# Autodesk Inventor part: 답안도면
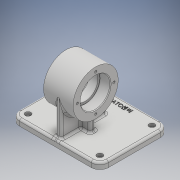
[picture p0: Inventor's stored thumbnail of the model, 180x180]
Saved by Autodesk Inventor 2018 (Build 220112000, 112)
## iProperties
Created: 2019-09
Part Number: 답안도면
Material: 일반
Document SubType Name: Modeling
Designer: USER
Density: 1 g/cm^3
Appearance: 기본값
Mass: 205.424 g
Surface Area: 495.891 cm^2
Volume: 205.424 cm^3
Author: USER
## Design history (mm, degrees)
sketch "스케치1"
  geometry: L1 (0, 0)-(42, 0); L2 (0, 0)-(0, 32); L3 (0, 32)-(42, 32); L4 (42, 32)-(42, 0); L5 (0, 21)-(15, 21); L6 (15, 21)-(15, 18); L7 (15, 18)-(27, 18); L8 (27, 18)-(27, 21); L9 (27, 21)-(42, 21)
  constraints: 18 end point, 4 perpendicular, 4 point on line, 3 horizontal, 1 vertical
  dimensions: "d0" = 42 distance of L1.start L1.end; "d1" = 42 diameter of L5 L1; "d2" = 64 diameter of L3 L1; "d3" = 36 diameter of L7 L1; "d4" = 15 distance between parallel lines of L2 L6; "d5" = 15 distance between parallel lines of L4 L8
revolve "회전1" sketch "스케치1" stored, may be unused: angle "d6" = 90 deg
node "작업 평면1"
sketch "스케치2"
  geometry: L1 (0, 32)-(42, 32) reference; L2 (21, 32)-(21, -32); L3 (0, -32)-(42, -32) reference; L4 (42, -21)-(42, 21) reference; L5 (0, -21)-(0, 21) reference; L6 (0, 0)-(42, 0); L7 (21, 0)-(84, 0); L8 (84, 0)-(84, 62); L9 (84, 62)-(-42, 62); L10 (-42, 62)-(-42, -36); L11 (-42, -36)-(84, -36); L12 (84, -36)-(84, 0); 2 further points
  constraints: 16 end point, 5 midpoint, 3 perpendicular, 1 point on line, 1 vertical
  dimensions: "d8" = 63 distance of L7.start L7.end; "d9" = 62 distance of L7.end L8.end; "d10" = 126 distance of L8.end L9.end; "d11" = 98 distance of L9.end L10.end; "d12" = 126 distance of L10.end L11.end
extrude "돌출1" join sketch "스케치2" distance "d13" = 9; taper "d14" = 0 deg
sketch "스케치3"
  geometry: L1 (0, -32)-(-42, -32) reference; L2 (-21, -32)-(-21, -50); L3 (-21, -50)-(-4, -50); L4 (-4, -50)-(-4, -32); L5 (-21, -50)-(-38, -50); L6 (-38, -50)-(-38, -32); L7 (-4, -32)-(-38, -32); L8 (-4, -32)-(-4, -28.095); L9 (-4, -28.095)-(-38, -28.095); L10 (-38, -28.095)-(-38, -32); 1 further point
  constraints: 18 end point, 4 perpendicular, 2 point on line, 1 collinear, 1 midpoint, 1 vertical
  dimensions: "d15" = 17 distance of L2.end L3.end; "d16" = 17 distance of L2.end L5.end
extrude "돌출2" join sketch "스케치3" stored distance "d17" = 8; taper "d18" = 0 deg
node "작업 평면2"
sketch "스케치4"
  geometry: L1 (62, -50)-(-36, -50) reference; L2 (62, -59)-(-36, -59) reference; L3 (-36, -59)-(-36, -50) reference; L4 (62, -50)-(-36, -50) reference; L5 (62, -59)-(62, -50) reference; L6 (32, 0)-(32, -50); L7 (-32, 0)-(-32, -50); L8 (32, -50)-(-32, -50); C1 r 32 at (0, 0) reference; A1 r 32 centre (0, 0) between (32, 0) and (-32, 0) reference; 1 further point
  constraints: 6 end point, 4 tangent, 2 perpendicular, 2 point on circle, 2 point on line, 1 collinear
feature "리브1" sketch "스케치4" dims "d19" = 1, "d20" = 8, "d21" = 0, "d22" = 0, "d23" = 1, "d24" = 1
sketch "스케치5"
  geometry: L1 (-42, 62)-(-42, -36) reference; L2 (-42, 13)-(84, 13); L3 (84, -36)-(84, 62) reference; L4 (-42, 13)-(-42, 50); L5 (84, 62)-(-42, 62) reference; L6 (21, 62)-(-30, 62); L7 (-30, 62)-(-30, 37.273); L8 (-42, 50)-(-24.665, 50); L9 (-42, 13)-(-42, -24); L10 (-42, -36)-(84, -36) reference; L11 (21, -36)-(-30, -36); L12 (-30, -36)-(-30, -11.448); L13 (-42, -24)-(-22.22, -24); 3 further points
  constraints: 18 end point, 8 point on line, 4 midpoint, 2 horizontal, 2 perpendicular
  dimensions: "d25" = 37 distance of L2.start L4.end; "d26" = 51 distance of L6.start L6.end; "d27" = 37 distance of L2.start L9.end; "d28" = 51 distance of L11.start L11.end
hole "구멍1" sketch "스케치5" at (-30, 50), (-30, -24) diameter "d29" = 4.5; stored, may be unused: countersink angle "d33" = 90 deg, drill point angle "d35" = 118 deg; dims "d30" = 6, "d31" = 8, "d32" = 4.4, "d34" = 100
fillet "모깎기1" dims "d36" = 12
sketch "스케치6" dims "d37" = 52
  geometry: C1 r 21 at (0, 0) reference; 3 further points
  constraints: 2 horizontal alignment, 1 coincident, 2 other
hole "구멍2" sketch "스케치6" at (26, 0) diameter "d38" = 3.242; stored, may be unused: countersink angle "d42" = 90 deg, drill point angle "d44" = 118 deg; dims "d39" = 8, "d40" = 8, "d41" = 4.4, "d43" = 10
sketch "스케치7"
  geometry: L1 (84, -24)-(84, 50) reference; L2 (72, 62)-(-30, 62) reference; 2 further points
  constraints: 1 other
  dimensions: "d48" = 63 distance from line of L1 point (21, 52); "d49" = 10 distance from line of L2 point (21, 52)
feature "엠보싱1" sketch "스케치7" dims "d0" = 42, "d1" = 42, "d2" = 64, "d3" = 36, "d4" = 15, "d5" = 15, "d50" = 0.5, "d51" = 0
fillet "모깎기2" dims "d52" = 0.3
chamfer "모따기1" distance "d53" = 1; stored, may be unused: second distance "d54" = 2, angle "d55" = 45 deg
fillet "모깎기3" dims "d56" = 3
fillet "모깎기4" dims "d57" = 3
fillet "모깎기5" dims "d58" = 3
node "작업 평면3"
node "솔리드1"
pattern_circular "원형 패턴1" dims angle "d46" = 360 deg
mirror "미러1"
mirror "미러2"
node "투영된 루프1"
other parameters: "d7" = -59
